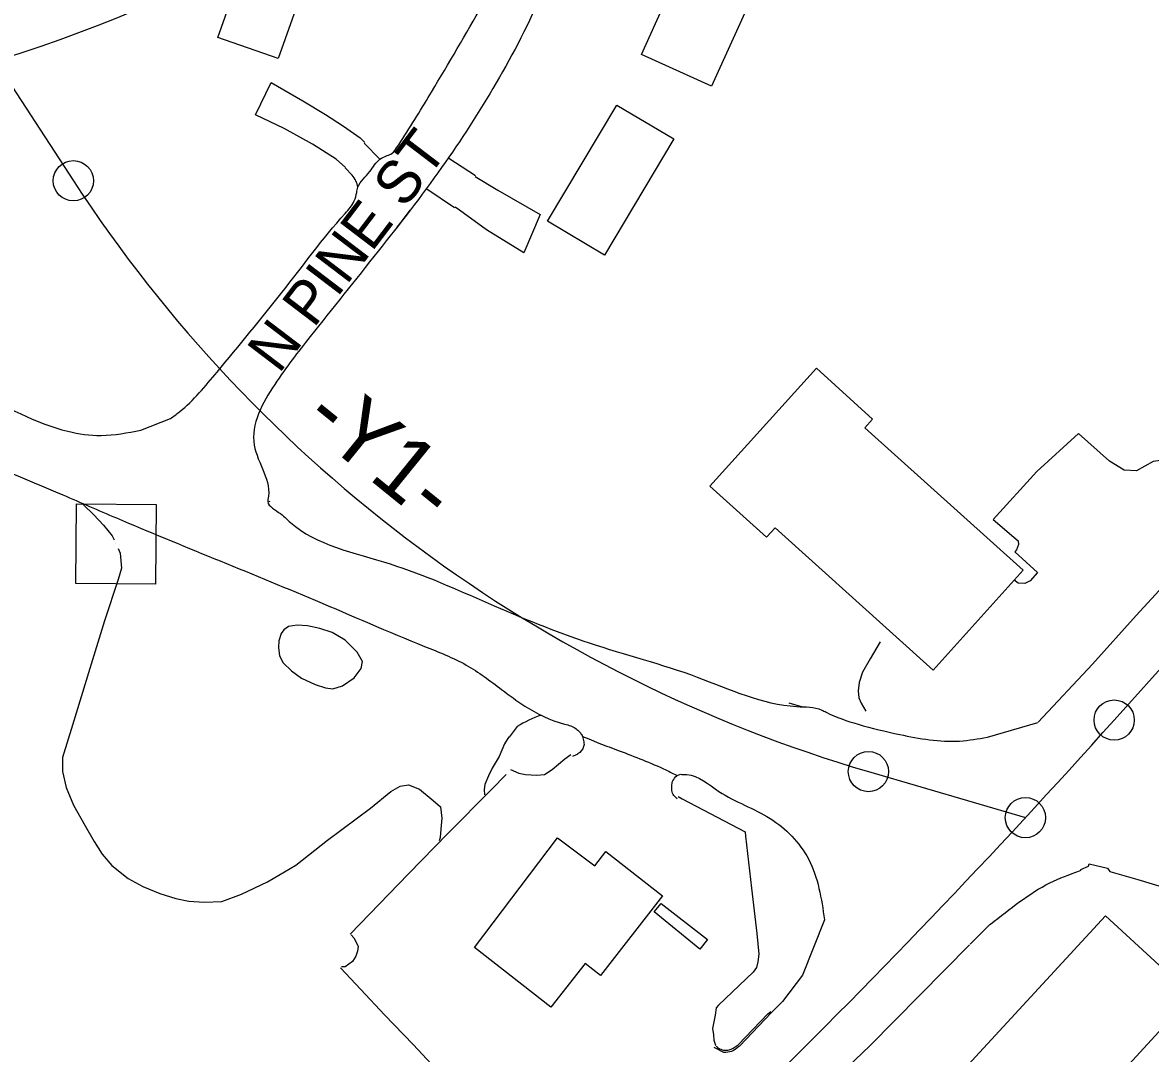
# Model space of a CAD drawing. Extents: x 2088830 to 2093930, y 861854 to 865154.
# Drawn here: x 2091261.6 to 2091682.1, y 863511.1 to 863895.4 of the extents above; entities that cross this region are included whole.
import ezdxf

# ---------------------------------------------------------------- set-up
doc = ezdxf.new("R2010")
doc.units = 0
for name, color, linetype in [('Default', 7, 'Continuous'), ('Exist Building', 7, 'Continuous'), ('Exist Horizontal Alignment', 7, 'Continuous'), ('Exist Horizontal Alignment Station Label', 7, 'Continuous'), ('Exist Roads Curbs', 7, 'Continuous'), ('Exist Roads EOP', 7, 'Continuous'), ('Exist Roads EOP Other', 7, 'Continuous'), ('Exist Roads EOP Text', 7, 'Continuous'), ('Exist Roads Soil', 7, 'Continuous')]:
    doc.layers.add(name, color=color, linetype=linetype)

msp = doc.modelspace()

# ---------------------------------------------------------------- linework, layer by layer
at = {"layer": 'Default'}
for p, q in [((2091668.57, 863635.39), (2092319.98, 864363.19)), ((2091251.42, 863881.05), (2091280.54, 863836.41)), ((2091296.31, 863701.03), (2091296.31, 863701.03)), ((2091576.95, 863616.18), (2091635.48, 863599.02))]:
    msp.add_line(p, q, dxfattribs=at)
msp.add_lwpolyline([(2091281.73, 863715.95), (2091311.38, 863715.71), (2091311.15, 863686.02), (2091281.5, 863686.25)], close=True, dxfattribs=at)
for centre, radius, start, end in [((2091085.24, 864421.06), 565, 247.6724, 295.7537), ((2091726.94, 864127.64), 533, 213.1208, 253.6565), ((2089433.17, 865636.13), 3000, 310.49872, 318.17058)]:
    msp.add_arc(centre, radius, start, end, dxfattribs=at)
at = {"layer": 'Exist Building'}
for p, q in [((2091497.12, 863563.86), (2091499.7, 863566.97)), ((2091499.7, 863566.97), (2091516.9, 863553.56)), ((2091514.15, 863549.99), (2091497.12, 863563.86)), ((2091516.9, 863553.56), (2091514.15, 863549.99))]:
    msp.add_line(p, q, dxfattribs=at)
for points in [[(2091370.53, 863920.51), (2091356.89, 863881.93), (2091334.42, 863889.87), (2091348.05, 863928.44)], [(2091538.91, 863916.88), (2091518.47, 863871.7), (2091492.32, 863883.53), (2091512.77, 863928.7)], [(2091504.37, 863852), (2091478.58, 863808.73), (2091457.36, 863821.38), (2091483.14, 863864.64)], [(2091575.61, 863744.38), (2091634.61, 863691.22), (2091601.05, 863654.01), (2091542.16, 863707.06), (2091538.94, 863703.55), (2091517.85, 863722.58), (2091557.55, 863766.5), (2091578.52, 863747.57)], [(2091430.07, 863550.64), (2091460.98, 863591.55), (2091474.9, 863581.03), (2091479.03, 863586.37), (2091500.2, 863569.85), (2091477.08, 863540.22), (2091471.36, 863544.62), (2091458.6, 863528.31)], [(2091665.32, 863562.47), (2091612.57, 863505.19), (2091635.21, 863484.35), (2091646.25, 863496.33), (2091655.98, 863487.38), (2091697.69, 863532.68)]]:
    msp.add_lwpolyline(points, close=True, dxfattribs=at)
at = {"layer": 'Exist Horizontal Alignment Station Label'}
for centre in [(2091280.54, 863836.41), (2091668.57, 863635.39), (2091576.95, 863616.18), (2091635.48, 863599.02)]:
    msp.add_circle(centre, 7.5, dxfattribs=at)
at = {"layer": 'Exist Roads Curbs'}
for points in [[(2091443.47, 863616.97), (2091446.57, 863615.57), (2091449.1, 863615.06), (2091453.29, 863614.85), (2091456.24, 863615.08), (2091459.04, 863616.94), (2091463.74, 863620.99), (2091465.99, 863622.57), (2091466.01, 863622.59)], [(2091383.7, 863555.64), (2091405.5, 863578.08), (2091420.19, 863593.12), (2091436.47, 863609.56), (2091441.95, 863615.14)], [(2091506.04, 863606.89), (2091507.45, 863606.08), (2091531.01, 863593.71), (2091531.16, 863592.1), (2091533.32, 863572.69), (2091535.29, 863555.85), (2091536.04, 863548.12), (2091535.77, 863545.25), (2091535.25, 863543.2), (2091534, 863541.43), (2091521.05, 863529.14), (2091520.24, 863528.16), (2091519.85, 863525.4), (2091518.85, 863520.45), (2091519.25, 863518.04), (2091519.28, 863516.11), (2091519.9, 863514.25), (2091520.06, 863514.09)], [(2091449.05, 863468.88), (2091435.94, 863484.07), (2091420.9, 863499.75), (2091407.18, 863514.47), (2091396.5, 863525.57), (2091387.74, 863534.92), (2091380.18, 863543.02)], [(2091528.02, 863514.06), (2091528.41, 863514.38), (2091539.41, 863525.84), (2091540.53, 863526.71)]]:
    msp.add_lwpolyline(points, dxfattribs=at)
msp.add_spline([(2091520.14, 863513.98), (2091520.93, 863513.18), (2091522.97, 863512.4), (2091525.04, 863512.46), (2091528.02, 863514.06)], degree=3, dxfattribs=at)
at = {"layer": 'Exist Roads EOP'}
for p, q in [((2091305.69, 863743.45), (2091316.71, 863747.76)), ((2091621.33, 863629.04), (2091640.08, 863634.42)), ((2091560.58, 863560.92), (2091552.41, 863540.24)), ((2091614.9, 863551.84), (2091621.94, 863558.96)), ((2091523.07, 863511.51), (2091519.47, 863513.36))]:
    msp.add_line(p, q, dxfattribs=at)
for points in [[(2091406, 863825.47), (2091402.66, 863820.99), (2091401.19, 863819.14)], [(2091734.18, 863736.92), (2091721.57, 863723.4), (2091693.87, 863693.03), (2091676.72, 863674.36), (2091660.52, 863656.21), (2091640.2, 863634.61)], [(2091353.49, 863717.09), (2091353.69, 863716.79)], [(2091547.32, 863641.76), (2091552.37, 863640.28)], [(2091470.37, 863629.28), (2091472.7, 863628.34), (2091476.5, 863626.75)], [(2091505.67, 863614.72), (2091506.22, 863615.03), (2091506.95, 863615.21)], [(2091655.69, 863579.19), (2091656.21, 863579.4), (2091656.13, 863579.68), (2091658.97, 863580.88), (2091659.28, 863581.75), (2091666.09, 863580.15), (2091666.95, 863578.98), (2091677.33, 863575.99), (2091705.32, 863567.54), (2091723.14, 863562.53), (2091739.84, 863556.32), (2091755.83, 863552.33), (2091778.96, 863545.71)], [(2091614.68, 863551.59), (2091577.53, 863513.94), (2091541.5, 863479.68), (2091509.96, 863450.67), (2091494.8, 863436.99), (2091459.99, 863406.66), (2091416.33, 863367.37), (2091398.26, 863350.73), (2091360.43, 863313.58), (2091358.8, 863312), (2091365.83, 863304.95)], [(2091552.39, 863540.36), (2091544.96, 863530.43), (2091540.8, 863526.33), (2091528.82, 863513.78)]]:
    msp.add_lwpolyline(points, dxfattribs=at)
for points in [[(2090168.38, 864198.76), (2090189.5, 864189.72), (2090230.53, 864172.75), (2090273.59, 864155.99), (2090314.47, 864138.57), (2090356.17, 864122.11), (2090401.7, 864102.94), (2090442.19, 864087.09), (2090481.45, 864070.2), (2090523.64, 864052.97), (2090568.11, 864034.48), (2090610.4, 864017.13), (2090655.12, 863999.01), (2090697.83, 863981.77), (2090742.36, 863964.54), (2090779.16, 863949.36), (2090823.64, 863930.17), (2090867.73, 863911.82), (2090910.45, 863894.46), (2090950.82, 863877.93), (2090971.61, 863869.44), (2091006.7, 863856.03), (2091045.62, 863839.26), (2091086.07, 863822.83), (2091122.3, 863807.64), (2091162.46, 863791.02), (2091203.94, 863773.83), (2091243.88, 863757.78), (2091278.52, 863743.03), (2091290.86, 863741.47), (2091305.69, 863743.45)], [(2090159.86, 864177.45), (2090180.67, 864168.73), (2090222.86, 864151.65), (2090264.39, 864134.6), (2090306, 864117.79), (2090347.24, 864101.05), (2090392.99, 864082.57), (2090433.2, 864065.09), (2090472.83, 864048.96), (2090514.73, 864032.43), (2090559.97, 864014.05), (2090601.37, 863997.19), (2090646.29, 863978.82), (2090688.95, 863961.27), (2090733.38, 863942.96), (2090770.05, 863927.33), (2090814.52, 863908.72), (2090858.91, 863891), (2090901.15, 863874.17), (2090939.87, 863858.28), (2090962.72, 863848.64), (2090997.54, 863834.72), (2091036.07, 863819.08), (2091075.6, 863802.48), (2091112.88, 863787.77), (2091153.64, 863770.65), (2091194.67, 863753.49), (2091234.07, 863737.23), (2091276.57, 863719.33), (2091296.56, 863710.75), (2091332.88, 863695.67), (2091370.71, 863680.05), (2091411.45, 863662.85), (2091427.01, 863655.9), (2091440.19, 863646.8), (2091448.83, 863640.62), (2091463.67, 863633.85), (2091467.99, 863632.17), (2091469.11, 863631.07), (2091469.97, 863630.04), (2091470.37, 863629.28)], [(2091458.63, 863915.3), (2091455.43, 863907.16), (2091438.17, 863872.89), (2091417.82, 863841.31), (2091394.13, 863810.14), (2091368.83, 863778.33), (2091355.6, 863760.48), (2091347.95, 863737.92), (2091353.05, 863717.6), (2091353.04, 863717.56), (2091357.07, 863712.82), (2091361.5, 863708.99), (2091398.61, 863693.57), (2091435.17, 863678.96), (2091472.88, 863664.14), (2091513.07, 863651.42), (2091550.28, 863640.44), (2091559.59, 863639.13), (2091561.17, 863638.35), (2091573.07, 863633.85), (2091588.61, 863630.02), (2091610.92, 863627.57), (2091621.33, 863629.04)], [(2091316.71, 863747.76), (2091320.13, 863750.32), (2091334.11, 863765.12), (2091358.4, 863794.91), (2091381.85, 863824.24), (2091385.28, 863828.95), (2091386.17, 863832.05), (2091386.64, 863833.99), (2091391.05, 863839.87), (2091394.85, 863844.48), (2091397.51, 863845.77), (2091399.36, 863846.66), (2091401.03, 863848.65), (2091412.87, 863867.49), (2091431.95, 863899.97)], [(2091476.5, 863626.75), (2091484, 863623.96), (2091501.41, 863616.8), (2091505.67, 863614.72)], [(2091506.95, 863615.21), (2091507.91, 863615.1), (2091509.2, 863615.04), (2091521.21, 863608.82), (2091540.28, 863598.73), (2091554.58, 863583.61), (2091560.58, 863560.92)], [(2091621.94, 863558.96), (2091622.43, 863559.34), (2091633.45, 863567.73), (2091644.6, 863574.68), (2091655.69, 863579.19)], [(2091528.82, 863513.78), (2091528.53, 863513.58), (2091525.94, 863511.89), (2091523.07, 863511.51)]]:
    msp.add_spline(points, degree=3, dxfattribs=at)
at = {"layer": 'Exist Roads EOP Other'}
for p, q in [((2091468, 863622.37), (2091466.68, 863621.75)), ((2091505.04, 863614.18), (2091505.52, 863614.59))]:
    msp.add_line(p, q, dxfattribs=at)
for points in [[(2091709.82, 863724.09), (2091710.43, 863726.63), (2091707.29, 863727.77), (2091704.98, 863728.48), (2091698.04, 863730.61), (2091692.89, 863732.2), (2091688.54, 863732.52), (2091683.12, 863731.81), (2091676.84, 863728.24), (2091672.3, 863728.53), (2091666.84, 863731.92), (2091655.29, 863742.21), (2091639.69, 863728.05), (2091623.47, 863710.19), (2091631.13, 863703.58), (2091632.8, 863702.2), (2091632.89, 863700.81), (2091632.16, 863698.88), (2091631.56, 863698.16), (2091640.02, 863690.43), (2091637.25, 863687.26), (2091635.22, 863686.33), (2091632.8, 863686.46), (2091631.33, 863687.59)], [(2091581.34, 863664.61), (2091577.55, 863658.19), (2091574.73, 863653.27), (2091573.52, 863649.35), (2091573.13, 863646.32), (2091573.32, 863643.67), (2091574.26, 863641.72), (2091576.02, 863638.76)], [(2091384.06, 863555.29), (2091385.1, 863554.27), (2091385.93, 863552.58), (2091386.69, 863550.96), (2091386.47, 863549.26), (2091385.9, 863547.42), (2091384.55, 863545.34), (2091381.83, 863543.37), (2091380.54, 863543.36)]]:
    msp.add_lwpolyline(points, dxfattribs=at)
for points in [[(2091470.42, 863629.24), (2091470.6, 863628.24), (2091470.92, 863626.3), (2091469.3, 863623.32), (2091468, 863622.37)], [(2091505.68, 863606.06), (2091505.13, 863606.49), (2091503.9, 863608.11), (2091503.63, 863610.27), (2091503.84, 863612.22), (2091505.04, 863614.18)]]:
    msp.add_spline(points, degree=3, dxfattribs=at)
at = {"layer": 'Exist Roads Soil'}
for p, q in [((2091394.85, 863844.49), (2091388.99, 863850.49)), ((2091420.46, 863844.84), (2091430.45, 863838.34)), ((2091384.47, 863838.5), (2091381.93, 863841.29)), ((2091422.57, 863826.36), (2091412.35, 863833.24)), ((2091445.98, 863633), (2091443.07, 863629.07)), ((2091417.23, 863591.56), (2091416.92, 863590.37))]:
    msp.add_line(p, q, dxfattribs=at)
for points in [[(2091382.01, 863841.42), (2091378.55, 863844.42), (2091369.75, 863850.06), (2091359.1, 863855.85), (2091348.47, 863861), (2091354.22, 863873.1), (2091366.1, 863866.17), (2091374.49, 863861.16), (2091381.27, 863856.73), (2091387.41, 863852.36), (2091389.17, 863850.68)], [(2091430.35, 863837.99), (2091438.77, 863832.97), (2091454.61, 863823.9), (2091448.44, 863809.58), (2091434.6, 863818.09), (2091424.52, 863825.47), (2091422.83, 863826.58)], [(2091284.17, 863715.77), (2091288.22, 863711.84), (2091291.83, 863708.05), (2091294.96, 863704.02), (2091295.79, 863702.6)], [(2091297.29, 863699.35), (2091297.95, 863697.54), (2091298.53, 863691.99), (2091297.25, 863687.82), (2091292.11, 863672.43), (2091286.65, 863654.66), (2091280.18, 863633.53), (2091276.5, 863621.38), (2091276.45, 863616.21), (2091277.9, 863610.29), (2091280.64, 863603.65), (2091284.88, 863595.92), (2091288.31, 863590.1), (2091291.23, 863585.38), (2091294.89, 863581.22), (2091300.91, 863576.31), (2091306.48, 863573.37), (2091312.82, 863570.75), (2091318.76, 863568.93), (2091323.55, 863567.94), (2091329.25, 863567.56), (2091335.92, 863567.82), (2091343.24, 863570.51), (2091352.97, 863575.08), (2091363.5, 863581.27), (2091375.34, 863590.58), (2091391.31, 863602.6), (2091398.86, 863608.82), (2091402.43, 863610.69), (2091405.43, 863611.25), (2091409.54, 863609.67), (2091414.73, 863605.45), (2091417.37, 863603.06), (2091417.93, 863598.79), (2091417.53, 863594.67), (2091417.23, 863591.56)], [(2091377.06, 863668.06), (2091372.38, 863669.49), (2091367.83, 863670.53), (2091364, 863670.72), (2091360.78, 863670.22), (2091358.95, 863669.02), (2091358.01, 863667.65), (2091357.2, 863664.94), (2091357.04, 863662.47), (2091357.37, 863659.37), (2091358.78, 863656.7), (2091361.86, 863653.68), (2091365.63, 863650.96), (2091370.74, 863648.63), (2091374.57, 863647.37), (2091377.33, 863647), (2091380.83, 863648.14), (2091385.24, 863651.09), (2091387.88, 863654.6), (2091388.35, 863657.27), (2091386.34, 863660.74), (2091381.81, 863665.22), (2091377.06, 863668.06)], [(2091442.94, 863629.15), (2091441.33, 863626.59), (2091439.22, 863621.8), (2091436.66, 863617.43), (2091435.32, 863614.64), (2091433.97, 863611.33), (2091433.75, 863609.53), (2091433.84, 863607.5)]]:
    msp.add_lwpolyline(points, dxfattribs=at)
for centre, major_axis, ratio, start_param, end_param in [((2091376.5, 863831.86), (0.22, 10.41), 0.994699, 4.94006, 5.425854), ((2091466.44, 863599.54), (-38.87, -21.43), 0.883314, 4.528871, 4.752092)]:
    msp.add_ellipse(centre, major_axis=major_axis, ratio=ratio, start_param=start_param, end_param=end_param, dxfattribs=at)

# ---------------------------------------------------------------- texts
at = {"layer": 'Exist Horizontal Alignment'}
msp.add_text('-Y1-', height=24, rotation=320.9723, dxfattribs=at).set_placement((2091365.22, 863745.79))
at = {"layer": 'Exist Roads EOP Text'}
msp.add_text('N PINE ST', height=16, rotation=52.7337, dxfattribs=at).set_placement((2091357.16, 863764.13))

doc.saveas('drawing.dxf')
